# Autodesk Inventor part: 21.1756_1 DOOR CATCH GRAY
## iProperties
Created: 2007-03
Part Number: 21.1756_1 DOOR CATCH GRAY
Document SubType Name: Modeling
Designer: Andy Moles
Material: ABS Plastic
Mass: 10.7547 g
Surface Area: 58.1955 cm^2
Volume: 10.1459 cm^3
Density: 1.06 g/cm^3
Author: Andy Moles
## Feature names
1. Base1
2. Extrusion1
3. Extrusion2
